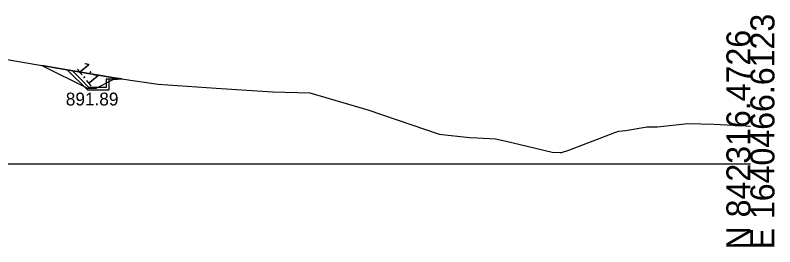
# Model space of a CAD drawing. Extents: x -26 to 1640245, y -10 to 842531.
# Drawn here: x 214.3 to 302.8, y -9.7 to 17.3 of the extents above; entities that cross this region are included whole.
import ezdxf

# ---------------------------------------------------------------- set-up
doc = ezdxf.new("R2010")
doc.units = 0
for name, color, linetype in [('Exist Cross Section Cell', 7, 'Continuous'), ('Exist XS Ground Line', 7, 'Continuous'), ('Prop CMT Concrete Ditch', 7, 'Continuous'), ('Prop XS Ditch Standard Text', 7, 'Continuous'), ('Prop XS Side Slope Text', 7, 'Continuous'), ('Scratch_Level_0', 7, 'Continuous'), ('Scratch_Level_2', 7, 'Continuous')]:
    doc.layers.add(name, color=color, linetype=linetype)

msp = doc.modelspace()

# ---------------------------------------------------------------- linework, layer by layer
at = {"layer": 'Exist Cross Section Cell'}
msp.add_line((150, 0), (300, 0), dxfattribs=at)
at = {"layer": 'Exist XS Ground Line'}
for p, q in [((205.339, 13.529), (221.519, 10.77)), ((221.519, 10.77), (225.843, 10.016)), ((225.843, 10.016), (226.128, 9.984)), ((226.128, 9.984), (226.424, 9.942)), ((226.424, 9.942), (230.981, 9.259)), ((230.981, 9.259), (237.753, 8.819)), ((237.753, 8.819), (244.312, 8.392)), ((244.312, 8.392), (248.645, 8.257)), ((248.645, 8.257), (255.414, 6.277)), ((255.414, 6.277), (263.733, 3.459)), ((289.166, 4.282), (292.709, 4.669)), ((292.709, 4.669), (295.736, 4.619)), ((295.736, 4.619), (299.507, 4.432)), ((299.507, 4.432), (300, 4.382)), ((278.842, 1.589), (284.206, 3.644)), ((284.206, 3.644), (284.654, 3.795)), ((284.654, 3.795), (285.422, 3.867)), ((285.422, 3.867), (287.97, 4.312)), ((287.97, 4.312), (289.166, 4.282)), ((263.733, 3.459), (267.281, 3.069)), ((267.281, 3.069), (268.169, 3.016)), ((268.169, 3.016), (270.293, 2.882)), ((270.293, 2.882), (271.547, 2.61)), ((271.547, 2.61), (273.181, 2.248)), ((273.181, 2.248), (276.884, 1.335)), ((276.884, 1.335), (277.814, 1.321)), ((277.814, 1.321), (277.998, 1.318)), ((277.998, 1.318), (278.842, 1.589))]:
    msp.add_line(p, q, dxfattribs=at)
at = {"layer": 'Prop CMT Concrete Ditch'}
for p, q in [((222.779, 8.56), (220.375, 10.965)), ((220.375, 10.965), (220.943, 10.868)), ((224.917, 9.893), (224.917, 8.893)), ((224.917, 9.893), (225.25, 9.893)), ((225.25, 9.893), (226.75, 9.893)), ((225.25, 9.893), (226.75, 9.893)), ((225.25, 9.893), (225.25, 8.56)), ((224.917, 8.893), (222.917, 8.893)), ((225.25, 8.56), (222.779, 8.56))]:
    msp.add_line(p, q, dxfattribs=at)
msp.add_lwpolyline([(222.917, 8.893), (221.917, 9.893), (220.943, 10.868)], dxfattribs=at)
at = {"layer": 'Scratch_Level_2'}
for p, q in [((217.439, 11.465), (222.75, 8.81)), ((223.75, 8.81), (225.75, 9.81)), ((225.75, 9.81), (226.75, 9.893)), ((222.75, 8.81), (223.75, 8.81))]:
    msp.add_line(p, q, dxfattribs=at)
msp.add_lwpolyline([(226.75, 9.893), (226.424, 9.942), (226.128, 9.984), (225.843, 10.016), (221.519, 10.77), (217.439, 11.465)], dxfattribs=at)

# ---------------------------------------------------------------- texts
at = {"layer": 'Exist Cross Section Cell'}
for s, p in [('E 1640466.6123', (302.8, -10)), ('N 842316.4726', (300, -10))]:
    msp.add_text(s, height=2.8, rotation=90, dxfattribs=at).set_placement(p)
at = {"layer": 'Prop XS Ditch Standard Text'}
msp.add_text('891.89', height=1.5, rotation=360, dxfattribs=at).set_placement((220.218, 6.789))
at = {"layer": 'Prop XS Side Slope Text'}
msp.add_text('1:1', height=1.5, rotation=309.22034, dxfattribs=at).set_placement((221.408, 11.092))
at = {"layer": 'Scratch_Level_0'}
for s, p in [('Exterior Boundary', (220.066, 11.003)), ('RT_Slope_Fill', (220.081, 11.003)), ('Exterior Boundary', (220.117, 10.995)), ('RT_Slope_Fill', (220.132, 10.995))]:
    msp.add_text(s, height=0.01, dxfattribs=at).set_placement(p)

doc.saveas('drawing.dxf')
